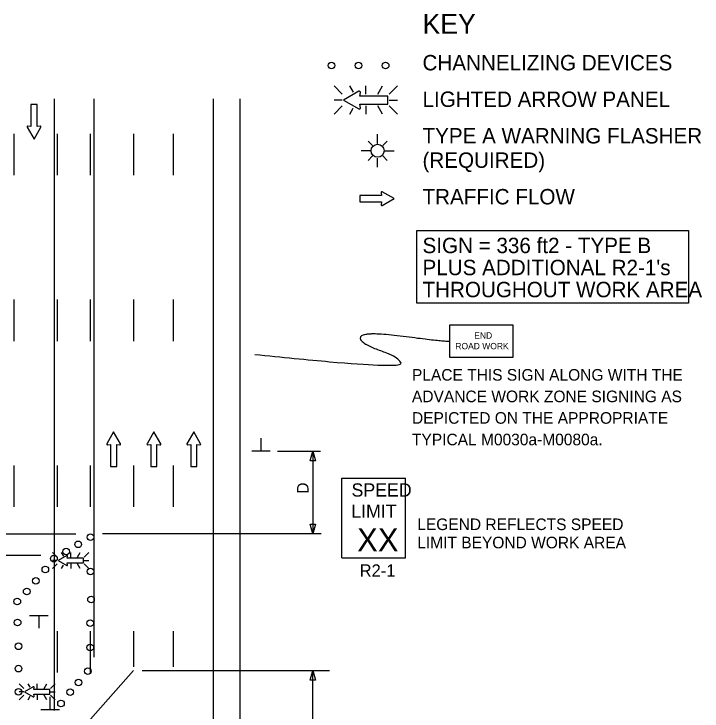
# Model space of a CAD drawing. Extents: x 16731 to 19504, y 5932 to 7446.
# Drawn here: x 17002.5 to 17417.4, y 6495.9 to 6916.4 of the extents above; entities that cross this region are included whole.
import ezdxf

# ---------------------------------------------------------------- set-up
doc = ezdxf.new("R2010")
doc.units = 0
for name, color, linetype in [('ALI_LEGAL_EX', 7, 'Continuous'), ('MT_SCRATCH_LEVEL_E', 7, 'Continuous'), ('PAVT_EDGE_EX', 7, 'Continuous'), ('TRAFFIC_SIGNS_PR', 7, 'Continuous'), ('TYPICAL_TEXT_DIMEN_EX', 7, 'Continuous'), ('TYPICAL_TEXT_DIMEN_PR', 7, 'Continuous')]:
    doc.layers.add(name, color=color, linetype=linetype)

msp = doc.modelspace()

# ---------------------------------------------------------------- linework, layer by layer
at = {"layer": 'ALI_LEGAL_EX'}
for points in [[(17002.71, 6819.12), (17002.71, 6844.12)], [(17028.71, 6819.12), (17028.71, 6844.12)], [(17048.71, 6819.12), (17048.71, 6844.12)], [(17074.71, 6819.12), (17074.71, 6844.12)], [(17098.71, 6819.12), (17098.71, 6844.12)], [(17002.71, 6719.12), (17002.71, 6744.12)], [(17028.71, 6719.12), (17028.71, 6744.12)], [(17048.71, 6719.12), (17048.71, 6744.12)], [(17074.71, 6719.12), (17074.71, 6744.12)], [(17098.71, 6719.12), (17098.71, 6744.12)], [(17002.71, 6619.12), (17002.71, 6644.12)], [(17028.71, 6619.12), (17028.71, 6644.12)], [(17048.71, 6619.12), (17048.71, 6644.12)], [(17074.71, 6619.12), (17074.71, 6644.12)], [(17098.71, 6619.12), (17098.71, 6644.12)], [(17028.71, 6519.12), (17028.71, 6544.12)], [(17048.71, 6519.12), (17048.71, 6544.12)], [(17074.71, 6522.64), (17074.71, 6544.12)], [(17098.71, 6522.64), (17098.71, 6544.12)]]:
    msp.add_lwpolyline(points, dxfattribs=at)
at = {"layer": 'MT_SCRATCH_LEVEL_E'}
for p, q in [((17016.45, 6861.76), (17012.71, 6861.76)), ((17012.71, 6861.76), (17012.71, 6848.5)), ((17016.45, 6861.76), (17012.71, 6861.76)), ((17012.71, 6861.76), (17012.71, 6848.5)), ((17016.45, 6848.5), (17016.45, 6861.76)), ((17016.45, 6848.5), (17016.45, 6861.76)), ((17010.45, 6848.13), (17014.6, 6840.89)), ((17010.45, 6848.13), (17014.6, 6840.89)), ((17012.71, 6848.5), (17010.93, 6848.82)), ((17012.71, 6848.5), (17010.93, 6848.82)), ((17014.6, 6840.89), (17018.71, 6848.13)), ((17014.6, 6840.89), (17018.71, 6848.13)), ((17018.23, 6848.82), (17016.45, 6848.5)), ((17018.23, 6848.82), (17016.45, 6848.5)), ((17223.9, 6808.68), (17224.22, 6806.9)), ((17223.9, 6808.68), (17224.22, 6806.9)), ((17231.83, 6805.05), (17224.59, 6809.16)), ((17231.83, 6805.05), (17224.59, 6809.16)), ((17224.22, 6806.9), (17210.96, 6806.9)), ((17210.96, 6806.9), (17210.96, 6803.16)), ((17224.22, 6806.9), (17210.96, 6806.9)), ((17210.96, 6806.9), (17210.96, 6803.16)), ((17224.59, 6800.9), (17231.83, 6805.05)), ((17224.59, 6800.9), (17231.83, 6805.05)), ((17210.96, 6803.16), (17224.22, 6803.16)), ((17210.96, 6803.16), (17224.22, 6803.16)), ((17224.22, 6803.16), (17223.9, 6801.38)), ((17224.22, 6803.16), (17223.9, 6801.38)), ((17062.58, 6664.37), (17058.47, 6657.13)), ((17062.58, 6664.37), (17058.47, 6657.13)), ((17066.73, 6657.13), (17062.58, 6664.37)), ((17066.73, 6657.13), (17062.58, 6664.37)), ((17086.85, 6664.37), (17082.74, 6657.13)), ((17086.85, 6664.37), (17082.74, 6657.13)), ((17090.99, 6657.13), (17086.85, 6664.37)), ((17090.99, 6657.13), (17086.85, 6664.37)), ((17110.92, 6664.37), (17106.81, 6657.13)), ((17110.92, 6664.37), (17106.81, 6657.13)), ((17115.07, 6657.13), (17110.92, 6664.37)), ((17115.07, 6657.13), (17110.92, 6664.37)), ((17058.95, 6656.44), (17060.73, 6656.76)), ((17058.95, 6656.44), (17060.73, 6656.76)), ((17060.73, 6656.76), (17060.73, 6643.5)), ((17060.73, 6656.76), (17060.73, 6643.5)), ((17064.47, 6643.5), (17064.47, 6656.76)), ((17064.47, 6656.76), (17066.25, 6656.44)), ((17064.47, 6643.5), (17064.47, 6656.76)), ((17064.47, 6656.76), (17066.25, 6656.44)), ((17083.22, 6656.44), (17085, 6656.76)), ((17083.22, 6656.44), (17085, 6656.76)), ((17085, 6656.76), (17085, 6643.5)), ((17085, 6656.76), (17085, 6643.5)), ((17088.74, 6643.5), (17088.74, 6656.76)), ((17088.74, 6656.76), (17090.52, 6656.44)), ((17088.74, 6643.5), (17088.74, 6656.76)), ((17088.74, 6656.76), (17090.52, 6656.44)), ((17107.29, 6656.44), (17109.07, 6656.76)), ((17107.29, 6656.44), (17109.07, 6656.76)), ((17109.07, 6656.76), (17109.07, 6643.5)), ((17109.07, 6656.76), (17109.07, 6643.5)), ((17112.81, 6643.5), (17112.81, 6656.76)), ((17112.81, 6656.76), (17114.59, 6656.44)), ((17112.81, 6643.5), (17112.81, 6656.76)), ((17112.81, 6656.76), (17114.59, 6656.44)), ((17060.73, 6643.5), (17064.47, 6643.5)), ((17060.73, 6643.5), (17064.47, 6643.5)), ((17085, 6643.5), (17088.74, 6643.5)), ((17085, 6643.5), (17088.74, 6643.5)), ((17109.07, 6643.5), (17112.81, 6643.5)), ((17109.07, 6643.5), (17112.81, 6643.5))]:
    msp.add_line(p, q, dxfattribs=at)
for centre, start, end in [((17010.86, 6848.36), 80.0362, 209.7731), ((17010.86, 6848.36), 80.0362, 209.7731), ((17018.3, 6848.36), 330.4248, 99.9638), ((17018.3, 6848.36), 330.4248, 99.9638), ((17224.36, 6808.75), 60.4248, 189.9638), ((17224.36, 6808.75), 60.4248, 189.9638), ((17224.36, 6801.31), 170.0362, 299.7731), ((17224.36, 6801.31), 170.0362, 299.7731), ((17058.88, 6656.9), 150.4248, 279.9638), ((17058.88, 6656.9), 150.4248, 279.9638), ((17066.32, 6656.9), 260.0362, 29.7731), ((17066.32, 6656.9), 260.0362, 29.7731), ((17083.14, 6656.9), 150.4248, 279.9638), ((17083.14, 6656.9), 150.4248, 279.9638), ((17090.59, 6656.9), 260.0362, 29.7731), ((17090.59, 6656.9), 260.0362, 29.7731), ((17107.22, 6656.9), 150.4248, 279.9638), ((17107.22, 6656.9), 150.4248, 279.9638), ((17114.66, 6656.9), 260.0362, 29.7731), ((17114.66, 6656.9), 260.0362, 29.7731)]:
    msp.add_arc(centre, 0.463, start, end, dxfattribs=at)
at = {"layer": 'PAVT_EDGE_EX'}
for p, q in [((17026.71, 6865.32), (17026.71, 6496.21)), ((17050.71, 6865.32), (17050.71, 6528.52)), ((17122.71, 6865.32), (17122.71, 6079.93)), ((17138.71, 6865.32), (17138.71, 6112.72)), ((17026.71, 6806.67), (17026.71, 6533.65)), ((17050.71, 6806.67), (17050.71, 6536.52))]:
    msp.add_line(p, q, dxfattribs=at)
at = {"layer": 'TRAFFIC_SIGNS_PR'}
for p, q in [((17195.51, 6872.99), (17200.44, 6868.05)), ((17207.27, 6869.16), (17205.07, 6872.99)), ((17214.59, 6868.05), (17214.59, 6872.99)), ((17221.83, 6868.05), (17224.68, 6872.99)), ((17228.74, 6868.05), (17233.68, 6872.99)), ((17200.44, 6864.5), (17195.51, 6864.5)), ((17228.74, 6864.5), (17233.68, 6864.5)), ((17195.51, 6856.01), (17200.44, 6860.94)), ((17205.02, 6856.01), (17207.14, 6859.67)), ((17214.59, 6860.94), (17214.59, 6856.01)), ((17224.72, 6856.01), (17221.87, 6860.94)), ((17228.74, 6860.94), (17233.68, 6856.01)), ((17221.8, 6838.34), (17221.8, 6843.96)), ((17221.8, 6838.34), (17221.8, 6843.96)), ((17218.66, 6837.03), (17216.03, 6839.67)), ((17218.66, 6837.03), (17216.03, 6839.67)), ((17224.93, 6837.03), (17227.57, 6839.67)), ((17224.93, 6837.03), (17227.57, 6839.67)), ((17217.86, 6833.9), (17211.82, 6833.9)), ((17217.86, 6833.9), (17211.82, 6833.9)), ((17225.73, 6833.9), (17231.83, 6833.9)), ((17225.73, 6833.9), (17231.83, 6833.9)), ((17218.66, 6830.76), (17216.03, 6828.13)), ((17218.66, 6830.76), (17216.03, 6828.13)), ((17221.8, 6823.95), (17221.8, 6829.46)), ((17221.8, 6823.95), (17221.8, 6829.46)), ((17224.93, 6830.76), (17227.56, 6828.13)), ((17224.93, 6830.76), (17227.56, 6828.13)), ((17200.28, 6636.43), (17238.68, 6636.43)), ((17200.28, 6588.43), (17200.28, 6636.43)), ((17238.68, 6588.43), (17238.68, 6636.43)), ((17025.79, 6591.61), (17028.61, 6588.79)), ((17032.51, 6589.43), (17031.25, 6591.61)), ((17036.7, 6588.79), (17036.7, 6591.61)), ((17040.83, 6588.79), (17042.46, 6591.61)), ((17044.78, 6588.79), (17047.6, 6591.61)), ((17028.61, 6586.76), (17025.79, 6586.76)), ((17044.78, 6586.76), (17047.6, 6586.76)), ((17200.28, 6588.43), (17238.68, 6588.43)), ((17025.79, 6581.91), (17028.61, 6584.73)), ((17031.23, 6581.91), (17032.44, 6584)), ((17036.7, 6584.73), (17036.7, 6581.91)), ((17042.49, 6581.91), (17040.86, 6584.73)), ((17044.78, 6584.73), (17047.6, 6581.91)), ((17005.58, 6512.42), (17008.4, 6509.61)), ((17012.3, 6510.24), (17011.04, 6512.43)), ((17016.49, 6509.61), (17016.49, 6512.43)), ((17020.62, 6509.61), (17022.25, 6512.43)), ((17024.57, 6509.61), (17027.39, 6512.43)), ((17008.4, 6507.57), (17005.58, 6507.57)), ((17005.58, 6502.72), (17008.4, 6505.54)), ((17016.49, 6505.54), (17016.49, 6502.72)), ((17022.28, 6502.72), (17020.65, 6505.54)), ((17024.57, 6507.57), (17027.39, 6507.57)), ((17024.57, 6505.54), (17027.39, 6502.72)), ((17011.02, 6502.72), (17012.22, 6504.82))]:
    msp.add_line(p, q, dxfattribs=at)
for points in [[(17210.52, 6869.77), (17201.23, 6864.5), (17210.52, 6859.18)], [(17211.4, 6859.8), (17210.99, 6862.07), (17228.01, 6862.07), (17228.01, 6866.87), (17210.99, 6866.87), (17211.4, 6869.15)], [(17034.37, 6589.78), (17029.06, 6586.76), (17034.37, 6583.72)], [(17034.87, 6584.08), (17034.64, 6585.37), (17044.36, 6585.37), (17044.36, 6588.12), (17034.64, 6588.12), (17034.87, 6589.42)], [(17014.16, 6510.59), (17008.85, 6507.57), (17014.16, 6504.53)], [(17014.66, 6504.89), (17014.43, 6506.19), (17024.15, 6506.19), (17024.15, 6508.93), (17014.43, 6508.93), (17014.66, 6510.24)]]:
    msp.add_lwpolyline(points, dxfattribs=at)
msp.add_lwpolyline([(17265.04, 6709.44), (17303.44, 6709.44), (17303.44, 6728.64), (17265.04, 6728.64)], close=True, dxfattribs=at)
for centre, radius in [((17194.02, 6885.34), 2), ((17210.32, 6885.34), 2), ((17226.62, 6885.34), 2), ((17221.8, 6833.9), 3.94), ((17221.8, 6833.9), 3.94), ((17048.6, 6600.8), 2), ((17048.6, 6600.8), 2), ((17041.27, 6596.49), 2), ((17033.94, 6592.19), 2), ((17026.61, 6587.88), 2), ((17021.41, 6581.36), 2), ((17048.65, 6580.13), 2), ((17015.7, 6574.44), 2), ((17010.17, 6568.05), 2), ((17048.96, 6563.18), 2), ((17004.51, 6562.04), 2), ((17004.71, 6549.39), 2), ((17048.52, 6548.9), 2), ((17005.21, 6535), 2), ((17005.21, 6535), 2), ((17048.52, 6534.26), 2), ((17005.21, 6521.52), 2), ((17046.98, 6520), 2), ((17041.48, 6513.17), 2), ((17005.21, 6507.59), 2), ((17036.36, 6507.3), 2), ((17030.86, 6500.47), 2)]:
    msp.add_circle(centre, radius, dxfattribs=at)
for centre, radius, start, end in [((17210.81, 6869.25), 0.598, 350.7308, 118.8916), ((17210.81, 6859.7), 0.597, 241.4833, 9.9593), ((17034.53, 6589.48), 0.341, 350.7308, 118.8916), ((17034.53, 6584.02), 0.341, 241.4833, 9.9593), ((17014.32, 6510.29), 0.341, 350.7308, 118.8916), ((17014.32, 6504.83), 0.341, 241.4833, 9.9593)]:
    msp.add_arc(centre, radius, start, end, dxfattribs=at)
at = {"layer": 'TYPICAL_TEXT_DIMEN_EX'}
msp.add_lwpolyline([(17245.52, 6785.85), (17409.26, 6785.85), (17409.26, 6741.9), (17245.52, 6741.9)], close=True, dxfattribs=at)
at = {"layer": 'TYPICAL_TEXT_DIMEN_PR'}
for p, q in [((17151.47, 6652.8), (17151.47, 6660.59)), ((17157.09, 6652.8), (17145.84, 6652.8)), ((17161.34, 6652.8), (17187.34, 6652.8)), ((17181.14, 6646.94), (17182.71, 6652.8)), ((17182.71, 6652.8), (17182.71, 6602.8)), ((17182.71, 6652.8), (17184.28, 6646.94)), ((17182.71, 6646.94), (17181.14, 6646.94)), ((17184.28, 6646.94), (17182.71, 6646.94)), ((17182.71, 6602.8), (17181.14, 6608.67)), ((17181.14, 6608.67), (17182.71, 6608.67)), ((17182.71, 6608.67), (17184.28, 6608.67)), ((17184.28, 6608.67), (17182.71, 6602.8)), ((16889.61, 6602.8), (17039.81, 6602.8)), ((17187.71, 6602.8), (17055.85, 6602.8)), ((17018.77, 6589.8), (16854.92, 6589.8)), ((17011.92, 6553.63), (17023.17, 6553.63)), ((17017.55, 6553.63), (17017.55, 6545.84)), ((17002.71, 6439.27), (17074.68, 6520.48)), ((17192.7, 6520.14), (17079.87, 6520.14)), ((17181.14, 6514.51), (17182.71, 6520.37)), ((17182.71, 6520.37), (17184.28, 6514.51)), ((17182.71, 6440.47), (17182.71, 6520.14)), ((17182.71, 6514.51), (17181.14, 6514.51)), ((17184.28, 6514.51), (17182.71, 6514.51)), ((17024.4, 6496.72), (17024.4, 6504.51)), ((17030.03, 6496.72), (17018.78, 6496.72))]:
    msp.add_line(p, q, dxfattribs=at)
msp.add_open_spline([(17147.74, 6711.08), (17235.64, 6701.86), (17235.64, 6709.13), (17210.19, 6717.91), (17213.03, 6725.31), (17260.12, 6719.04), (17265.04, 6719.04)], degree=2, dxfattribs=at)

# ---------------------------------------------------------------- texts
at = {"layer": 'TRAFFIC_SIGNS_PR'}
for s, height, p in [('END', 3.831, (17280.05, 6720.57)), ('ROAD WORK', 3.831, (17268.65, 6714.18)), ('PLACE THIS SIGN ALONG WITH THE', 7, (17242.5, 6695.24)), ('ADVANCE WORK ZONE SIGNING AS', 7, (17242.5, 6682.24)), ('DEPICTED ON THE APPROPRIATE', 7, (17242.5, 6669.24)), ('TYPICAL M0030a-M0080a.', 7, (17242.5, 6656.24)), ('SPEED', 8, (17206.05, 6625.29)), ('LIMIT', 8, (17205.88, 6612.49)), ('XX', 14.031, (17209.39, 6592.19)), ('R2-1', 7.44, (17210.96, 6576.99))]:
    msp.add_text(s, height=height, dxfattribs=at).set_placement(p)
at = {"layer": 'TYPICAL_TEXT_DIMEN_EX'}
for s, height, p in [('KEY', 12, (17248.86, 6904.45)), ('CHANNELIZING DEVICES', 9.3, (17248.86, 6882.4)), ('LIGHTED ARROW PANEL', 9.3, (17248.86, 6860.35)), ('TYPE A WARNING FLASHER', 9.3, (17248.86, 6838.3)), ('(REQUIRED)', 9.3, (17248.86, 6823.6)), ('TRAFFIC FLOW', 9.3, (17248.86, 6801.55)), ('SIGN = 336 ft2 - TYPE B', 9.3, (17248.86, 6772.15)), ("PLUS ADDITIONAL R2-1's", 9.3, (17248.86, 6758.85)), ('THROUGHOUT WORK AREA', 9.3, (17248.86, 6745.55))]:
    msp.add_text(s, height=height, dxfattribs=at).set_placement(p)
at = {"layer": 'TYPICAL_TEXT_DIMEN_PR'}
msp.add_text('D', height=7, rotation=90, dxfattribs=at).set_placement((17180.15, 6627.02))
for s, p in [('LEGEND REFLECTS SPEED', (17245.69, 6605.09)), ('LIMIT BEYOND WORK AREA', (17245.69, 6594.09))]:
    msp.add_text(s, height=7, dxfattribs=at).set_placement(p)

doc.saveas('drawing.dxf')
